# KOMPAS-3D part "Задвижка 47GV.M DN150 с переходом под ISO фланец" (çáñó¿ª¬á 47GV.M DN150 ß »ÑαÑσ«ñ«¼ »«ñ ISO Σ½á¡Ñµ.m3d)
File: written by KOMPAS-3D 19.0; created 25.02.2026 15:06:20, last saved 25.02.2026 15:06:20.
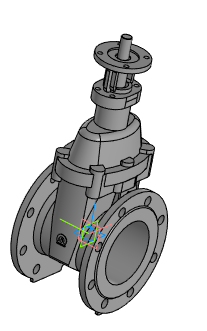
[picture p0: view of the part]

Document properties: Автор: Энергия; Полное имя файла: 47GV.M DN150\Задвижка 47GV.M DN150 с маховиком.a3d

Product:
- Part/product: Задвижка 47GV.M DN150 с переходом под ISO фланец
    Масса: 53.3836
  - Component: Задвижка с обрезиненным клином DN125. Сборочный чертеж  | designation DR.47GVM.125.16.00.00СБ  | pos. 0  | Масса: 25.3494; Раздел спецификации: Документация; Форматы листов документа: 2xA3; source file: 47GV.M DN150\DR.47GVM.125.16.00.000 СБ - Задвижка с обрезиненным клином DN125.cdw

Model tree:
1. Операция без истории:1

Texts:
  Точка начала. Х
  Точка начала. Y
  Точка начала. Z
